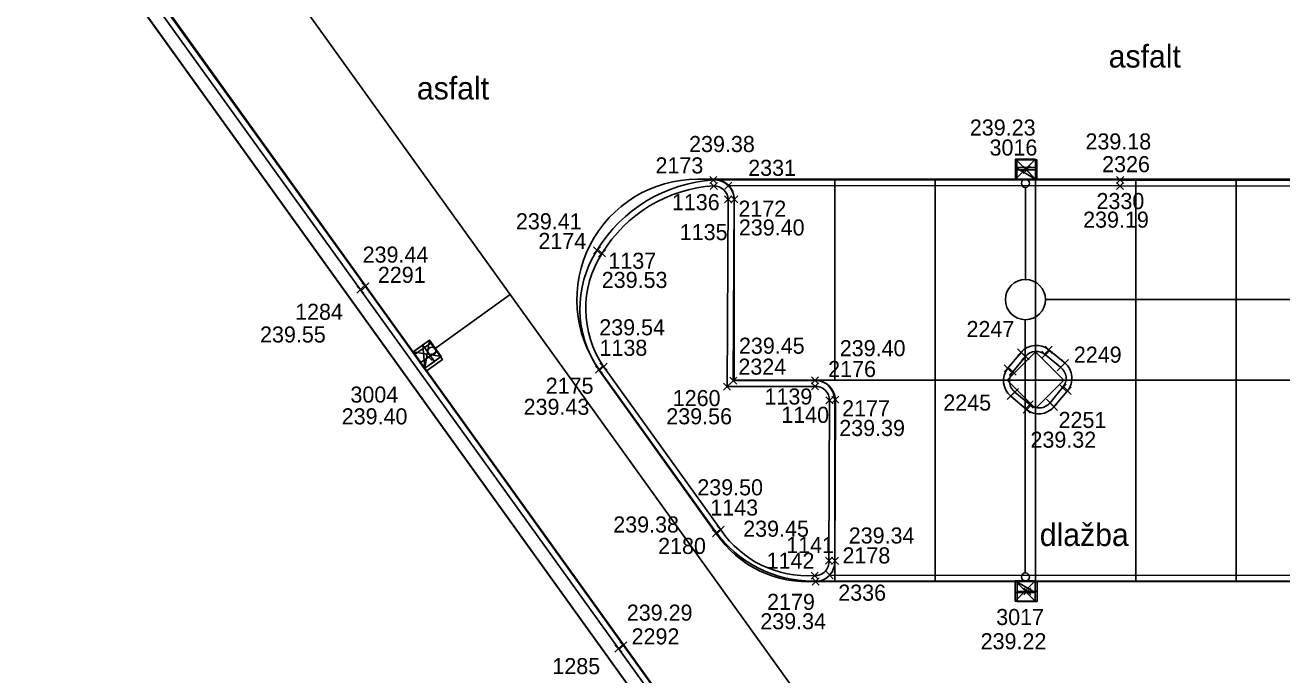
# Model space of a CAD drawing. Extents: x -264222 to -263676, y -1242344 to -1242060.
# Drawn here: x -264179.73 to -264148.43, y -1242246.81 to -1242230.65 of the extents above; entities that cross this region are included whole.
import ezdxf

# ---------------------------------------------------------------- set-up
doc = ezdxf.new("R2010")
doc.units = 0
for name, color, linetype in [('BODY_CISLO', 7, 'Continuous'), ('BODY_SYMBOL', 7, 'Continuous'), ('BODY_VYSKA', 7, 'Continuous'), ('BODY_VYSKY_UV', 7, 'Continuous'), ('KOORDINACNA_SITUACIA_DSP', 7, 'Continuous'), ('POPIS', 7, 'Continuous'), ('PROJEKT_DRS_OBRUBNIKY_KOMUNIKACIE', 7, 'Continuous'), ('PROJEKT_DRS_TDZ_VODOROVNE', 7, 'Continuous'), ('PROJEKT_DRS_UV_STAVBY', 7, 'Continuous'), ('SO_20-3_OBRUBNIKY_DOLNA_HRANA', 7, 'Continuous'), ('SO_20-3_OBRUBNIKY_HORNA_HRANA', 7, 'Continuous'), ('ULICNA_VPUST_POKLOP', 7, 'Continuous')]:
    doc.layers.add(name, color=color, linetype=linetype)

msp = doc.modelspace()

# ---------------------------------------------------------------- linework, layer by layer
at = {"layer": 'BODY_SYMBOL'}
for p, q in [((-264154.874, -1242234.335), (-264154.698, -1242234.159)), ((-264154.698, -1242234.335), (-264154.874, -1242234.159)), ((-264162.675, -1242234.586), (-264162.499, -1242234.41)), ((-264162.499, -1242234.586), (-264162.675, -1242234.41)), ((-264162.666, -1242234.734), (-264162.49, -1242234.558)), ((-264162.49, -1242234.734), (-264162.666, -1242234.558)), ((-264162.307, -1242234.728), (-264162.131, -1242234.552)), ((-264162.131, -1242234.728), (-264162.307, -1242234.552)), ((-264152.55, -1242234.736), (-264152.374, -1242234.56)), ((-264152.374, -1242234.736), (-264152.55, -1242234.56)), ((-264152.547, -1242234.59), (-264152.371, -1242234.414)), ((-264152.371, -1242234.59), (-264152.547, -1242234.414)), ((-264162.308, -1242235.068), (-264162.132, -1242234.892)), ((-264162.132, -1242235.068), (-264162.308, -1242234.892)), ((-264162.158, -1242235.069), (-264161.982, -1242234.893)), ((-264161.982, -1242235.069), (-264162.158, -1242234.893)), ((-264165.575, -1242236.34), (-264165.399, -1242236.164)), ((-264165.399, -1242236.34), (-264165.575, -1242236.164)), ((-264165.448, -1242236.413), (-264165.272, -1242236.237)), ((-264165.272, -1242236.413), (-264165.448, -1242236.237)), ((-264171.34, -1242237.237), (-264171.164, -1242237.061)), ((-264171.164, -1242237.237), (-264171.34, -1242237.061)), ((-264171.466, -1242237.319), (-264171.29, -1242237.143)), ((-264171.29, -1242237.319), (-264171.466, -1242237.143)), ((-264154.326, -1242238.813), (-264154.15, -1242238.637)), ((-264154.15, -1242238.813), (-264154.326, -1242238.637)), ((-264169.77, -1242238.994), (-264169.594, -1242238.818)), ((-264169.594, -1242238.994), (-264169.77, -1242238.818)), ((-264155.015, -1242238.876), (-264154.839, -1242238.7)), ((-264154.839, -1242238.876), (-264155.015, -1242238.7)), ((-264154.904, -1242238.976), (-264154.728, -1242238.8)), ((-264154.728, -1242238.976), (-264154.904, -1242238.8)), ((-264154.407, -1242238.936), (-264154.231, -1242238.76)), ((-264154.231, -1242238.936), (-264154.407, -1242238.76)), ((-264153.921, -1242239.144), (-264153.745, -1242238.968)), ((-264153.745, -1242239.144), (-264153.921, -1242238.968)), ((-264165.528, -1242239.308), (-264165.352, -1242239.132)), ((-264165.352, -1242239.308), (-264165.528, -1242239.132)), ((-264165.412, -1242239.23), (-264165.236, -1242239.054)), ((-264165.236, -1242239.23), (-264165.412, -1242239.054)), ((-264155.35, -1242239.276), (-264155.174, -1242239.1)), ((-264155.174, -1242239.276), (-264155.35, -1242239.1)), ((-264155.222, -1242239.359), (-264155.046, -1242239.183)), ((-264155.046, -1242239.359), (-264155.222, -1242239.183)), ((-264154.032, -1242239.248), (-264153.856, -1242239.072)), ((-264153.856, -1242239.248), (-264154.032, -1242239.072)), ((-264162.335, -1242239.728), (-264162.159, -1242239.552)), ((-264162.159, -1242239.728), (-264162.335, -1242239.552)), ((-264162.18, -1242239.583), (-264162.004, -1242239.407)), ((-264162.004, -1242239.583), (-264162.18, -1242239.407)), ((-264160.148, -1242239.575), (-264159.972, -1242239.399)), ((-264159.972, -1242239.575), (-264160.148, -1242239.399)), ((-264160.145, -1242239.724), (-264159.969, -1242239.548)), ((-264159.969, -1242239.724), (-264160.145, -1242239.548)), ((-264153.98, -1242239.753), (-264153.804, -1242239.577)), ((-264153.804, -1242239.753), (-264153.98, -1242239.577)), ((-264159.785, -1242240.069), (-264159.609, -1242239.893)), ((-264159.609, -1242240.069), (-264159.785, -1242239.893)), ((-264159.638, -1242240.056), (-264159.462, -1242239.88)), ((-264159.462, -1242240.056), (-264159.638, -1242239.88)), ((-264155.273, -1242239.963), (-264155.097, -1242239.787)), ((-264155.097, -1242239.963), (-264155.273, -1242239.787)), ((-264155.167, -1242239.864), (-264154.991, -1242239.688)), ((-264154.991, -1242239.864), (-264155.167, -1242239.688)), ((-264153.855, -1242239.833), (-264153.679, -1242239.657)), ((-264153.679, -1242239.833), (-264153.855, -1242239.657)), ((-264154.878, -1242240.3), (-264154.702, -1242240.124)), ((-264154.702, -1242240.3), (-264154.878, -1242240.124)), ((-264154.801, -1242240.174), (-264154.625, -1242239.998)), ((-264154.625, -1242240.174), (-264154.801, -1242239.998)), ((-264154.294, -1242240.13), (-264154.118, -1242239.954)), ((-264154.118, -1242240.13), (-264154.294, -1242239.954)), ((-264154.196, -1242240.234), (-264154.02, -1242240.058)), ((-264154.02, -1242240.234), (-264154.196, -1242240.058)), ((-264162.612, -1242243.377), (-264162.436, -1242243.201)), ((-264162.436, -1242243.377), (-264162.612, -1242243.201)), ((-264162.493, -1242243.292), (-264162.317, -1242243.116)), ((-264162.317, -1242243.292), (-264162.493, -1242243.116)), ((-264159.798, -1242244.063), (-264159.622, -1242243.887)), ((-264159.622, -1242244.063), (-264159.798, -1242243.887)), ((-264159.651, -1242244.065), (-264159.475, -1242243.889)), ((-264159.475, -1242244.065), (-264159.651, -1242243.889)), ((-264160.155, -1242244.431), (-264159.979, -1242244.255)), ((-264159.979, -1242244.431), (-264160.155, -1242244.255)), ((-264159.782, -1242244.42), (-264159.606, -1242244.244)), ((-264159.606, -1242244.42), (-264159.782, -1242244.244)), ((-264160.127, -1242244.578), (-264159.951, -1242244.402)), ((-264159.951, -1242244.578), (-264160.127, -1242244.402)), ((-264154.862, -1242244.824), (-264154.686, -1242244.648)), ((-264154.686, -1242244.824), (-264154.862, -1242244.648)), ((-264165.039, -1242246.247), (-264164.863, -1242246.071)), ((-264164.863, -1242246.247), (-264165.039, -1242246.071)), ((-264164.918, -1242246.167), (-264164.742, -1242245.991)), ((-264164.742, -1242246.167), (-264164.918, -1242245.991))]:
    msp.add_line(p, q, dxfattribs=at)
at = {"layer": 'KOORDINACNA_SITUACIA_DSP'}
for p, q in [((-264204.694, -1242191.482), (-264122.859, -1242305.266)), ((-264204.078, -1242191.482), (-264122.243, -1242305.266)), ((-264181.951, -1242217.458), (-264153.34, -1242257.238)), ((-264155.068, -1242234.192), (-264154.568, -1242234.192)), ((-264155.068, -1242234.482), (-264155.068, -1242234.192)), ((-264155.068, -1242234.192), (-264154.568, -1242234.482)), ((-264155.068, -1242234.192), (-264154.568, -1242234.482)), ((-264154.568, -1242234.192), (-264155.068, -1242234.192)), ((-264154.568, -1242234.192), (-264154.568, -1242234.482)), ((-264154.568, -1242234.482), (-264154.568, -1242234.192)), ((-264162.988, -1242234.482), (-264162.568, -1242234.482)), ((-264154.568, -1242234.482), (-264155.068, -1242234.482)), ((-264154.818, -1242234.682), (-264154.818, -1242236.976)), ((-264162.068, -1242239.482), (-264162.068, -1242234.982)), ((-264169.518, -1242238.695), (-264167.646, -1242237.348)), ((-264154.318, -1242237.476), (-264124.354, -1242237.476)), ((-264154.824, -1242244.276), (-264154.824, -1242237.976)), ((-264170.062, -1242238.778), (-264169.827, -1242238.609)), ((-264169.827, -1242238.609), (-264169.535, -1242239.015)), ((-264169.827, -1242238.609), (-264169.77, -1242239.184)), ((-264169.827, -1242238.609), (-264169.77, -1242239.184)), ((-264169.535, -1242239.015), (-264169.827, -1242238.609)), ((-264169.77, -1242239.184), (-264170.062, -1242238.778)), ((-264169.535, -1242239.015), (-264169.77, -1242239.184)), ((-264169.77, -1242239.184), (-264169.535, -1242239.015)), ((-264165.423, -1242239.234), (-264162.546, -1242243.234)), ((-264162.068, -1242239.482), (-264160.068, -1242239.482)), ((-264159.568, -1242239.982), (-264159.568, -1242244.482)), ((-264160.111, -1242244.482), (-264159.568, -1242244.482)), ((-264155.074, -1242244.476), (-264154.574, -1242244.476)), ((-264155.074, -1242244.766), (-264155.074, -1242244.476)), ((-264155.074, -1242244.476), (-264154.574, -1242244.766)), ((-264155.074, -1242244.476), (-264154.574, -1242244.766)), ((-264154.574, -1242244.476), (-264155.074, -1242244.476)), ((-264154.574, -1242244.476), (-264154.574, -1242244.766)), ((-264154.574, -1242244.766), (-264154.574, -1242244.476)), ((-264154.574, -1242244.766), (-264155.074, -1242244.766))]:
    msp.add_line(p, q, dxfattribs=at)
msp.add_lwpolyline([(-264204.694, -1242191.482), (-264137.78, -1242284.52), (-264125.581, -1242301.482)], dxfattribs=at)
msp.add_lwpolyline([(-264153.861, -1242239.482), (-264154.568, -1242238.775), (-264155.275, -1242239.482), (-264154.568, -1242240.189)], close=True, dxfattribs=at)
for centre, radius in [((-264154.818, -1242234.582), 0.1), ((-264154.818, -1242237.476), 0.5), ((-264169.597, -1242238.757), 0.1), ((-264154.818, -1242244.376), 0.1)]:
    msp.add_circle(centre, radius, dxfattribs=at)
for centre, radius, start, end in [((-264162.988, -1242237.482), 3, 90, 215.724), ((-264162.568, -1242234.982), 0.5, 0, 90), ((-264160.068, -1242239.982), 0.5, 0, 90), ((-264160.111, -1242241.482), 3, 215.724, 270)]:
    msp.add_arc(centre, radius, start, end, dxfattribs=at)
at = {"layer": 'PROJEKT_DRS_OBRUBNIKY_KOMUNIKACIE'}
for p, q in [((-264204.694, -1242191.482), (-264115.871, -1242314.982)), ((-264204.078, -1242191.482), (-264119.571, -1242308.982)), ((-264162.988, -1242234.482), (-264162.568, -1242234.482)), ((-264134.568, -1242234.482), (-264162.528, -1242234.482)), ((-264162.068, -1242239.482), (-264162.068, -1242234.982)), ((-264154.568, -1242238.775), (-264155.275, -1242239.482)), ((-264153.861, -1242239.482), (-264154.568, -1242238.775)), ((-264154.568, -1242238.775), (-264154.568, -1242240.189)), ((-264154.568, -1242240.189), (-264154.568, -1242238.775)), ((-264165.423, -1242239.234), (-264162.546, -1242243.234)), ((-264162.068, -1242239.482), (-264160.068, -1242239.482)), ((-264155.275, -1242239.482), (-264154.568, -1242240.189)), ((-264154.568, -1242240.189), (-264153.861, -1242239.482)), ((-264159.568, -1242239.982), (-264159.568, -1242244.482)), ((-264160.111, -1242244.482), (-264159.568, -1242244.482)), ((-264159.568, -1242244.482), (-264134.568, -1242244.482))]:
    msp.add_line(p, q, dxfattribs=at)
msp.add_lwpolyline([(-264204.694, -1242191.482), (-264137.78, -1242284.52), (-264125.581, -1242301.482)], dxfattribs=at)
for centre, radius, start, end in [((-264162.988, -1242237.482), 3, 90, 215.724), ((-264162.568, -1242234.982), 0.5, 0, 90), ((-264160.068, -1242239.982), 0.5, 0, 90), ((-264160.111, -1242241.482), 3, 215.724, 270)]:
    msp.add_arc(centre, radius, start, end, dxfattribs=at)
at = {"layer": 'PROJEKT_DRS_TDZ_VODOROVNE'}
for p, q in [((-264159.568, -1242239.482), (-264159.568, -1242234.482)), ((-264157.068, -1242239.482), (-264157.068, -1242234.482)), ((-264154.568, -1242239.482), (-264154.568, -1242234.482)), ((-264152.068, -1242239.482), (-264152.068, -1242234.482)), ((-264149.568, -1242239.482), (-264149.568, -1242234.482)), ((-264134.568, -1242239.482), (-264160.068, -1242239.482)), ((-264157.068, -1242244.482), (-264157.068, -1242239.482)), ((-264154.568, -1242244.482), (-264154.568, -1242239.482)), ((-264152.068, -1242244.482), (-264152.068, -1242239.482)), ((-264149.568, -1242244.482), (-264149.568, -1242239.482))]:
    msp.add_line(p, q, dxfattribs=at)
at = {"layer": 'PROJEKT_DRS_UV_STAVBY'}
for points in [[(-264155.068, -1242234.482), (-264155.068, -1242233.982), (-264154.568, -1242233.982), (-264154.568, -1242234.482), (-264155.068, -1242234.482), (-264154.568, -1242233.982), (-264155.068, -1242233.982), (-264154.568, -1242234.482)], [(-264169.77, -1242239.184), (-264170.062, -1242238.778), (-264169.656, -1242238.486), (-264169.364, -1242238.892), (-264169.77, -1242239.184), (-264169.656, -1242238.486), (-264170.062, -1242238.778), (-264169.364, -1242238.892)], [(-264155.074, -1242244.976), (-264155.074, -1242244.476), (-264154.574, -1242244.476), (-264154.574, -1242244.976), (-264155.074, -1242244.976), (-264154.574, -1242244.476), (-264155.074, -1242244.476), (-264154.574, -1242244.976)]]:
    msp.add_lwpolyline(points, dxfattribs=at)
at = {"layer": 'SO_20-3_OBRUBNIKY_DOLNA_HRANA'}
for p, q in [((-264155.262, -1242239.188), (-264154.927, -1242238.788)), ((-264154.238, -1242238.725), (-264153.833, -1242239.056)), ((-264165.44, -1242239.22), (-264162.524, -1242243.289)), ((-264155.185, -1242239.875), (-264154.79, -1242240.212)), ((-264153.767, -1242239.745), (-264154.108, -1242240.146)), ((-264159.563, -1242243.977), (-264159.55, -1242239.968))]:
    msp.add_line(p, q, dxfattribs=at)
for points in [[(-264179.08, -1242196.474), (-264200.47, -1242196.472), (-264195.765, -1242203.023), (-264189.923, -1242211.168), (-264184.11, -1242219.268), (-264178.281, -1242227.391), (-264171.252, -1242237.149), (-264164.83, -1242246.079), (-264158.406, -1242254.997), (-264151.981, -1242263.929), (-264145.549, -1242272.885), (-264139.496, -1242281.305), (-264132.148, -1242291.541), (-264125.165, -1242301.265), (-264124.808, -1242301.762)], [(-264162.587, -1242234.498), (-264152.459, -1242234.502), (-264145.453, -1242234.512), (-264134.079, -1242234.517)], [(-264134.414, -1242234.651), (-264145.455, -1242234.655), (-264152.462, -1242234.648), (-264162.219, -1242234.64)], [(-264160.06, -1242239.487), (-264162.092, -1242239.495), (-264162.07, -1242234.981)], [(-264160.039, -1242244.49), (-264147.118, -1242244.488), (-264134.128, -1242244.469)], [(-264134.432, -1242244.333), (-264147.12, -1242244.339), (-264159.694, -1242244.332)]]:
    msp.add_lwpolyline(points, dxfattribs=at)
for centre, major_axis, ratio, start_param, end_param in [((-264162.358, -1242238.147), (-3.305, -1.587), 0.99683, 4.328458, 5.289463), ((-264162.568, -1242234.996), (0.294, 0.402), 0.999899, 5.374447, 6.95317), ((-264163.235, -1242237.701), (-0.654, 2.598), 0.999523, 0.752461, 1.926952), ((-264154.55, -1242239.115), (-0.377, -0.328), 0.997946, 3.320393, 4.851604), ((-264154.867, -1242239.492), (0.056, -0.495), 0.999568, 3.946065, 5.478713), ((-264154.163, -1242239.435), (-0.048, 0.5), 0.999974, 3.953189, 5.471588), ((-264160.05, -1242239.988), (0.2, 0.459), 0.999806, 5.161595, 6.712261), ((-264154.484, -1242239.822), (-0.012, 0.496), 0.999846, 2.451819, 3.977559), ((-264160.243, -1242241.74), (0.866, -2.618), 0.999835, 4.989518, 6.03786), ((-264160.057, -1242243.996), (0.167, 0.465), 0.99994, 3.522654, 5.095759)]:
    msp.add_ellipse(centre, major_axis=major_axis, ratio=ratio, start_param=start_param, end_param=end_param, dxfattribs=at)
at = {"layer": 'SO_20-3_OBRUBNIKY_HORNA_HRANA'}
for p, q in [((-264162.22, -1242234.98), (-264162.247, -1242239.64)), ((-264155.134, -1242239.271), (-264154.816, -1242238.888)), ((-264154.319, -1242238.848), (-264153.944, -1242239.16)), ((-264162.405, -1242243.204), (-264165.324, -1242239.142)), ((-264160.057, -1242239.636), (-264162.247, -1242239.64)), ((-264154.713, -1242240.086), (-264155.079, -1242239.776)), ((-264153.892, -1242239.665), (-264154.206, -1242240.042)), ((-264159.697, -1242239.981), (-264159.71, -1242243.975))]:
    msp.add_line(p, q, dxfattribs=at)
msp.add_lwpolyline([(-264204.226, -1242191.388), (-264204.22, -1242191.499), (-264200.55, -1242196.62), (-264195.884, -1242203.112), (-264190.046, -1242211.249), (-264184.226, -1242219.352), (-264178.398, -1242227.475), (-264171.378, -1242237.231), (-264164.951, -1242246.159), (-264158.525, -1242255.075), (-264152.106, -1242264.005), (-264145.671, -1242272.964), (-264139.631, -1242281.361), (-264132.272, -1242291.613), (-264125.285, -1242301.347), (-264124.926, -1242301.846)], dxfattribs=at)
for centre, major_axis, ratio, start_param, end_param in [((-264162.374, -1242238.124), (-3.186, -1.429), 0.997648, 4.349882, 5.31793), ((-264162.571, -1242234.997), (-0.243, 0.253), 0.999304, 3.996539, 5.537807), ((-264163.224, -1242237.707), (0.329, -2.524), 0.999091, 4.009032, 5.182125), ((-264154.549, -1242239.116), (-0.277, -0.218), 0.995594, 3.337489, 4.909693), ((-264154.864, -1242239.497), (0.028, -0.352), 0.997585, 3.936992, 5.544473), ((-264154.153, -1242239.437), (-0.036, 0.345), 0.999343, 3.891428, 5.53335), ((-264160.045, -1242239.984), (-0.325, 0.127), 0.999504, 3.52328, 5.117695), ((-264154.481, -1242239.817), (0.307, -0.178), 0.99916, 4.526604, 6.123782), ((-264160.242, -1242241.732), (1.337, -2.25), 0.999608, 4.77386, 5.813921), ((-264160.051, -1242244.002), (0.334, 0.073), 0.999776, 4.45006, 6.14598)]:
    msp.add_ellipse(centre, major_axis=major_axis, ratio=ratio, start_param=start_param, end_param=end_param, dxfattribs=at)
at = {"layer": 'ULICNA_VPUST_POKLOP'}
for p, q in [((-264154.786, -1242234.247), (-264154.786, -1242234.247)), ((-264169.682, -1242238.906), (-264169.682, -1242238.906)), ((-264154.774, -1242244.736), (-264154.774, -1242244.736))]:
    msp.add_line(p, q, dxfattribs=at)
for points in [[(-264155.036, -1242234.247), (-264155.036, -1242233.997), (-264154.536, -1242233.997), (-264154.536, -1242234.497), (-264155.036, -1242234.497), (-264155.036, -1242234.247), (-264154.536, -1242234.247)], [(-264169.887, -1242239.049), (-264170.03, -1242238.845), (-264169.621, -1242238.558), (-264169.334, -1242238.967), (-264169.743, -1242239.254), (-264169.887, -1242239.049), (-264169.477, -1242238.763)], [(-264155.024, -1242244.736), (-264155.024, -1242244.486), (-264154.524, -1242244.486), (-264154.524, -1242244.986), (-264155.024, -1242244.986), (-264155.024, -1242244.736), (-264154.524, -1242244.736)]]:
    msp.add_lwpolyline(points, dxfattribs=at)

# ---------------------------------------------------------------- texts
at = {"layer": 'BODY_CISLO'}
for s, p in [('3016', (-264155.712, -1242233.891)), ('2173', (-264164.03, -1242234.336)), ('2326', (-264152.909, -1242234.305)), ('2331', (-264161.721, -1242234.396)), ('1136', (-264163.622, -1242235.251)), ('2330', (-264153.049, -1242235.223)), ('2172', (-264161.965, -1242235.413)), ('2174', (-264166.945, -1242236.215)), ('1135', (-264163.426, -1242235.996)), ('1137', (-264165.203, -1242236.709)), ('2291', (-264170.943, -1242237.06)), ('1284', (-264173.004, -1242237.979)), ('2247', (-264156.285, -1242238.408)), ('1138', (-264165.424, -1242238.875)), ('2249', (-264153.613, -1242239.046)), ('2324', (-264161.966, -1242239.344)), ('2176', (-264159.73, -1242239.402)), ('2175', (-264166.764, -1242239.819)), ('3004', (-264171.626, -1242240.039)), ('1260', (-264163.6, -1242240.126)), ('1139', (-264161.316, -1242240.087)), ('2245', (-264156.863, -1242240.238)), ('1140', (-264160.898, -1242240.543)), ('2177', (-264159.382, -1242240.38)), ('2251', (-264153.993, -1242240.67)), ('1143', (-264162.665, -1242242.85)), ('2180', (-264163.965, -1242243.805)), ('1141', (-264160.775, -1242243.781)), ('2178', (-264159.374, -1242244.041)), ('1142', (-264161.263, -1242244.172)), ('2336', (-264159.479, -1242244.968)), ('2179', (-264161.251, -1242245.197)), ('3017', (-264155.546, -1242245.574)), ('2292', (-264164.625, -1242246.056)), ('1285', (-264166.598, -1242246.796))]:
    msp.add_text(s, height=0.4, dxfattribs=at).set_placement(p)
at = {"layer": 'BODY_VYSKA'}
for s, p in [('239.18', (-264153.324, -1242233.74)), ('239.38', (-264163.193, -1242233.804)), ('239.41', (-264167.505, -1242235.727)), ('239.40', (-264161.954, -1242235.88)), ('239.19', (-264153.382, -1242235.686)), ('239.44', (-264171.322, -1242236.556)), ('239.53', (-264165.368, -1242237.186)), ('239.54', (-264165.43, -1242238.365)), ('239.55', (-264173.877, -1242238.543)), ('239.45', (-264161.952, -1242238.823)), ('239.40', (-264159.441, -1242238.884)), ('239.43', (-264167.314, -1242240.343)), ('239.56', (-264163.761, -1242240.579)), ('239.39', (-264159.454, -1242240.87)), ('239.32', (-264154.693, -1242241.162)), ('239.50', (-264162.989, -1242242.347)), ('239.38', (-264165.082, -1242243.272)), ('239.45', (-264161.846, -1242243.377)), ('239.34', (-264159.218, -1242243.545)), ('239.29', (-264164.744, -1242245.465)), ('239.34', (-264161.42, -1242245.679))]:
    msp.add_text(s, height=0.4, dxfattribs=at).set_placement(p)
at = {"layer": 'BODY_VYSKY_UV'}
for s, p in [('239.23', (-264156.202, -1242233.393)), ('239.40', (-264171.843, -1242240.581)), ('239.22', (-264155.933, -1242246.177))]:
    msp.add_text(s, height=0.4, dxfattribs=at).set_placement(p)
at = {"layer": 'POPIS'}
for p in [(-264152.745, -1242231.701), (-264169.972, -1242232.496)]:
    msp.add_text('asfalt', height=0.5625, dxfattribs=at).set_placement(p)
msp.add_text('dlažba', height=0.5625, rotation=360, dxfattribs=at).set_placement((-264154.462, -1242243.607))

doc.saveas('drawing.dxf')
